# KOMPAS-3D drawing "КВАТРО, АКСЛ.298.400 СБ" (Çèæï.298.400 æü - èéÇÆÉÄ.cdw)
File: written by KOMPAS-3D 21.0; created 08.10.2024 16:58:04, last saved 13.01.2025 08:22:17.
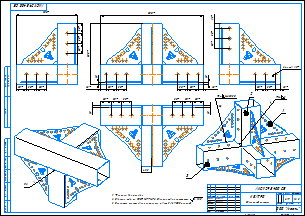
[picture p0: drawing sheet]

Sheet 1: A2, landscape

Document properties: Полное имя файла: КВАТРО сборка.a3d; Автор: Алексей Бочаров; Масса: 6.994498

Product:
- Part/product: КВАТРО  | designation АКСЛ.298.400 СБ
    Масса: 6.994498
    Форматы листов документа: A4
    source file: АКСЛ.298.400 - КВАТРО.spw
  - Component [detail]: Профиль L = 200 мм  | designation АКСЛ.298.401  | qty 2  | pos. 2  | Масса: 1.210897; source file: Профиль L = 200 мм.cdw, Профиль L = 200 мм.m3d
  - Component [assembly]: Перемычка  | designation АКСЛ.298.201  | qty 5  | pos. 1  | Масса: 0.308618; source file: ..\Перемычка.stp
  - Component [detail]: Профиль L = 500 мм  | designation АКСЛ.298.402  | pos. 3  | Масса: 3.029613; source file: Профиль L = 500 мм.cdw, Профиль L = 500 мм.m3d

Title block, sheet 1: Наименование: КВАТРО / Сборочный чертеж; designation: АКСЛ.298.400 СБ; Масса: 6,99; Количество листов документа: 1; organisation: ООО "Аксель"; Форматы листов документа: A2; stored path: C:\Users\Алексей Бочаров\Desktop\Соединения бруса\КВАТРО\КВАТРО Сборочный чертеж.cdw; Разработал: Бочаров; Проверил: Захаров; Утвердил: Гелетей

Referenced files in C:\Users\79253\YandexDisk\Соединения бруса\Соединения бруса\КВАТРО\: Профиль L = 200 мм.m3d, Профиль L = 200 мм.cdw, Профиль L = 500 мм.m3d, Профиль L = 500 мм.cdw, КВАТРО сборка.a3d
Referenced files in C:\Users\79253\YandexDisk\Соединения бруса\Соединения бруса\: Перемычка.stp
Referenced files in C:\Users\Алексей Бочаров\Desktop\Соединения бруса\КВАТРО\: КВАТРО сборка.a3d
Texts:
  АКСЛ.298.401
  Профиль L = 200 мм
  АКСЛ.298.201
  Перемычка
  АКСЛ.298.402
  Профиль L = 500 мм
  АКСЛ.298.400
  АКСЛ.298.402 Профиль L = 500 мм
  АКСЛ.298.401 Профиль L = 200 мм
  АКСЛ.298.201 Перемычка
  АКСЛ.298.400 СБ КВАТРО
Dimensions and other numbers on the sheet: 2; 5; 1; 1:2,5; 6,99; 3D Узел_3; 3D Узел_3 3D Узел_3; 3D Узел_2; 3D Узел_2 3D Узел_2; 0; 0 0

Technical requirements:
  *Размеры для справок.
  Сварные швы по ГОСТ 14771-76. Сварные швы зачистить  Ra 12,5.
  Покрытие порошковое полимерное, цвет RAL 9005 черный.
